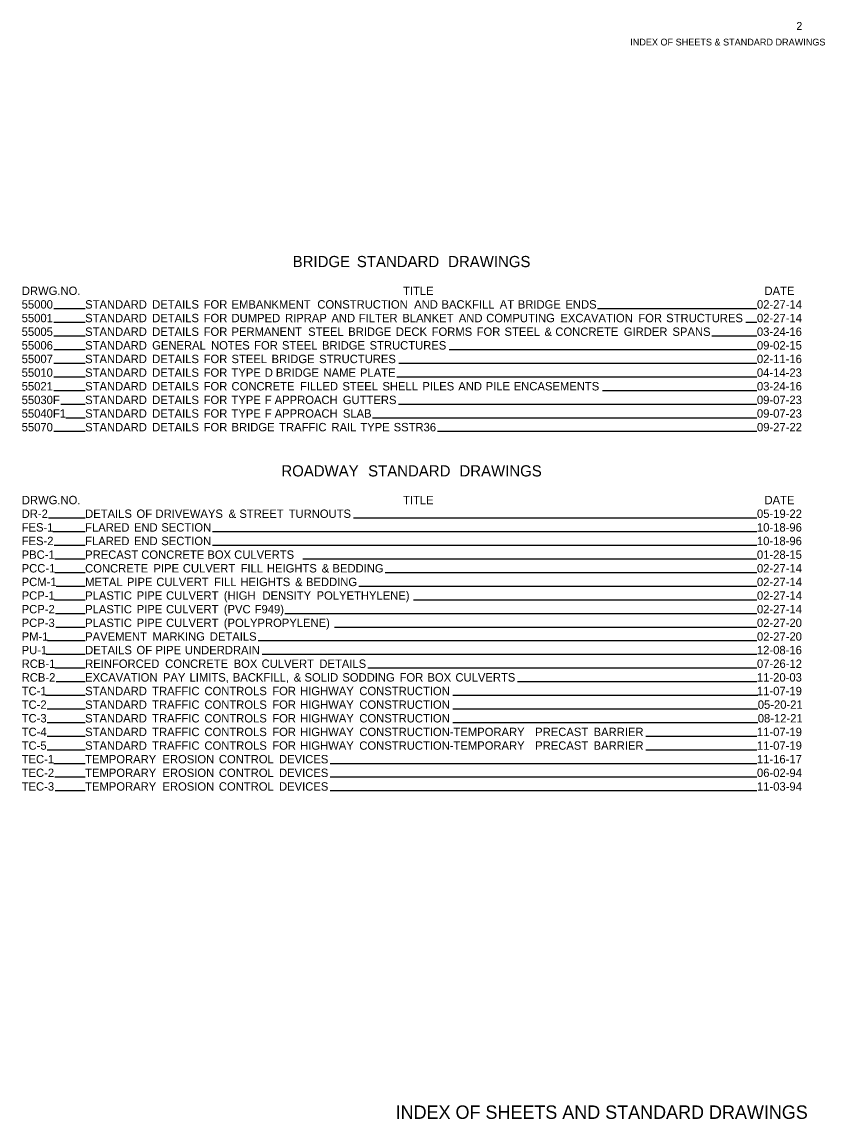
# Model space of a CAD drawing. Extents: x 1334719.7 to 1334768.4, y 402732.4 to 402752.
# Drawn here: x 1334754.07 to 1334768.42, y 402732.35 to 402751.96 of the extents above; entities that cross this region are included whole.
import ezdxf

# ---------------------------------------------------------------- set-up
doc = ezdxf.new("R2010")
doc.units = 0
for name, color, linetype in [('Default', 7, 'Continuous'), ('R_No Plot', 7, 'Continuous'), ('T_Drafting', 7, 'Continuous')]:
    doc.layers.add(name, color=color, linetype=linetype)

msp = doc.modelspace()

# ---------------------------------------------------------------- linework, layer by layer
at = {"layer": 'Default'}
for p, q in [((1334754.642, 402746.84), (1334755.203, 402746.84)), ((1334764.358, 402746.84), (1334767.208, 402746.84)), ((1334754.642, 402746.596), (1334755.203, 402746.596)), ((1334767.009, 402746.596), (1334767.208, 402746.596)), ((1334754.642, 402746.352), (1334755.203, 402746.352)), ((1334766.4, 402746.352), (1334767.207, 402746.352)), ((1334754.642, 402746.108), (1334755.203, 402746.108)), ((1334761.709, 402746.108), (1334767.207, 402746.108)), ((1334754.642, 402745.865), (1334755.203, 402745.865)), ((1334760.808, 402745.865), (1334767.207, 402745.865)), ((1334754.642, 402745.621), (1334755.203, 402745.621)), ((1334760.77, 402745.621), (1334767.207, 402745.621)), ((1334754.642, 402745.377), (1334755.203, 402745.377)), ((1334764.449, 402745.377), (1334767.207, 402745.377)), ((1334754.77, 402745.133), (1334755.203, 402745.133)), ((1334760.801, 402745.133), (1334767.207, 402745.133)), ((1334754.858, 402744.89), (1334755.203, 402744.89)), ((1334760.335, 402744.89), (1334767.207, 402744.89)), ((1334754.642, 402744.646), (1334755.203, 402744.646)), ((1334761.501, 402744.646), (1334767.208, 402744.646)), ((1334754.547, 402743.098), (1334755.203, 402743.098)), ((1334759.996, 402743.098), (1334767.208, 402743.098)), ((1334754.625, 402742.854), (1334755.203, 402742.854)), ((1334757.481, 402742.854), (1334767.207, 402742.854)), ((1334754.652, 402742.611), (1334755.203, 402742.611)), ((1334757.481, 402742.611), (1334767.207, 402742.611)), ((1334754.66, 402742.367), (1334755.203, 402742.367)), ((1334759.094, 402742.367), (1334767.208, 402742.367)), ((1334754.66, 402742.123), (1334755.203, 402742.123)), ((1334760.567, 402742.123), (1334767.208, 402742.123)), ((1334754.683, 402741.879), (1334755.203, 402741.879)), ((1334760.093, 402741.879), (1334767.208, 402741.879)), ((1334754.648, 402741.636), (1334755.203, 402741.636)), ((1334761.069, 402741.636), (1334767.208, 402741.636)), ((1334754.676, 402741.392), (1334755.203, 402741.392)), ((1334758.774, 402741.392), (1334767.208, 402741.392)), ((1334754.677, 402741.148), (1334755.203, 402741.148)), ((1334759.656, 402741.148), (1334767.208, 402741.148)), ((1334754.532, 402740.904), (1334755.203, 402740.904)), ((1334758.296, 402740.904), (1334767.208, 402740.904)), ((1334754.508, 402740.661), (1334755.203, 402740.661)), ((1334758.368, 402740.661), (1334767.208, 402740.661)), ((1334754.66, 402740.417), (1334755.203, 402740.417)), ((1334760.253, 402740.417), (1334767.207, 402740.417)), ((1334754.687, 402740.173), (1334755.203, 402740.173)), ((1334762.929, 402740.173), (1334767.207, 402740.173)), ((1334754.497, 402739.929), (1334755.203, 402739.929)), ((1334761.776, 402739.929), (1334767.222, 402739.929)), ((1334754.524, 402739.686), (1334755.203, 402739.686)), ((1334761.776, 402739.686), (1334767.222, 402739.686)), ((1334754.526, 402739.442), (1334755.203, 402739.442)), ((1334761.776, 402739.442), (1334767.222, 402739.442)), ((1334754.525, 402739.198), (1334755.203, 402739.198)), ((1334765.221, 402739.198), (1334767.207, 402739.198)), ((1334754.527, 402738.954), (1334755.203, 402738.954)), ((1334765.221, 402738.954), (1334767.207, 402738.954)), ((1334754.642, 402738.711), (1334755.203, 402738.711)), ((1334759.58, 402738.711), (1334767.207, 402738.711)), ((1334754.664, 402738.467), (1334755.203, 402738.467)), ((1334759.58, 402738.467), (1334767.208, 402738.467)), ((1334754.665, 402738.223), (1334755.203, 402738.223)), ((1334759.58, 402738.223), (1334767.208, 402738.223))]:
    msp.add_line(p, q, dxfattribs=at)

# ---------------------------------------------------------------- texts
for s, height, p in [('BRIDGE', 0.2, (1334758.911, 402747.581)), (' STANDARD', 0.2, (1334759.984, 402747.581)), (' DRAWINGS', 0.2, (1334761.615, 402747.581)), ('DRWG.NO.', 0.15, (1334754.072, 402747.083)), ('TITLE', 0.15, (1334760.883, 402747.083)), ('DATE', 0.15, (1334767.342, 402747.083)), ('55000', 0.15, (1334754.069, 402746.84)), ('STANDARD', 0.15, (1334755.203, 402746.84)), (' DETAILS', 0.15, (1334756.345, 402746.84)), (' FOR', 0.15, (1334757.265, 402746.84)), (' EMBANKMENT', 0.15, (1334757.763, 402746.84)), (' CONSTRUCTION', 0.15, (1334759.296, 402746.84)), (' AND', 0.15, (1334761.026, 402746.84)), (' BACKFILL', 0.15, (1334761.515, 402746.84)), (' AT', 0.15, (1334762.556, 402746.84)), (' BRIDGE', 0.15, (1334762.878, 402746.84)), (' ENDS', 0.15, (1334763.729, 402746.84)), ('02-27-14', 0.15, (1334767.208, 402746.84)), ('55001', 0.15, (1334754.069, 402746.596)), ('STANDARD', 0.15, (1334755.203, 402746.596)), (' DETAILS', 0.15, (1334756.345, 402746.596)), (' FOR', 0.15, (1334757.265, 402746.596)), (' DUMPED', 0.15, (1334757.763, 402746.596)), (' RIPRAP', 0.15, (1334758.719, 402746.596)), (' AND', 0.15, (1334759.548, 402746.596)), (' FILTER', 0.15, (1334760.038, 402746.596)), (' BLANKET', 0.15, (1334760.815, 402746.596)), (' AND', 0.15, (1334761.824, 402746.596)), (' COMPUTING', 0.15, (1334762.314, 402746.596)), (' EXCAVATION', 0.15, (1334763.64, 402746.596)), (' FOR', 0.15, (1334765.032, 402746.596)), (' STRUCTURES', 0.15, (1334765.53, 402746.596)), ('02-27-14', 0.15, (1334767.208, 402746.596)), ('55005', 0.15, (1334754.069, 402746.352)), ('STANDARD', 0.15, (1334755.203, 402746.352)), (' DETAILS', 0.15, (1334756.345, 402746.352)), (' FOR', 0.15, (1334757.265, 402746.352)), (' PERMANENT', 0.15, (1334757.763, 402746.352)), (' STEEL', 0.15, (1334759.133, 402746.352)), (' BRIDGE', 0.15, (1334759.848, 402746.352)), (' DECK', 0.15, (1334760.699, 402746.352)), (' FORMS', 0.15, (1334761.339, 402746.352)), (' FOR', 0.15, (1334762.143, 402746.352)), (' STEEL', 0.15, (1334762.641, 402746.352)), (' &', 0.15, (1334763.355, 402746.352)), (' CONCRETE', 0.15, (1334763.549, 402746.352)), (' GIRDER', 0.15, (1334764.772, 402746.352)), (' SPANS', 0.15, (1334765.642, 402746.352)), ('03-24-16', 0.15, (1334767.207, 402746.352)), ('55006', 0.15, (1334754.069, 402746.108)), ('STANDARD', 0.15, (1334755.203, 402746.108)), (' GENERAL', 0.15, (1334756.345, 402746.108)), (' NOTES', 0.15, (1334757.397, 402746.108)), (' FOR', 0.15, (1334758.167, 402746.108)), (' STEEL', 0.15, (1334758.664, 402746.108)), (' BRIDGE', 0.15, (1334759.379, 402746.108)), (' STRUCTURES', 0.15, (1334760.23, 402746.108)), ('09-02-15', 0.15, (1334767.207, 402746.108)), ('55007', 0.15, (1334754.069, 402745.865)), ('STANDARD', 0.15, (1334755.203, 402745.865)), (' DETAILS', 0.15, (1334756.345, 402745.865)), (' FOR', 0.15, (1334757.265, 402745.865)), (' STEEL', 0.15, (1334757.763, 402745.865)), (' BRIDGE', 0.15, (1334758.478, 402745.865)), (' STRUCTURES', 0.15, (1334759.329, 402745.865)), ('02-11-16', 0.15, (1334767.207, 402745.865)), ('55010', 0.15, (1334754.069, 402745.621)), ('STANDARD', 0.15, (1334755.203, 402745.621)), (' DETAILS', 0.15, (1334756.345, 402745.621)), (' FOR', 0.15, (1334757.265, 402745.621)), (' TYPE', 0.15, (1334757.763, 402745.621)), (' D', 0.15, (1334758.358, 402745.621)), (' BRIDGE', 0.15, (1334758.556, 402745.621)), (' NAME', 0.15, (1334759.407, 402745.621)), (' PLATE', 0.15, (1334760.059, 402745.621)), ('04-14-23', 0.15, (1334767.207, 402745.621)), ('55021', 0.15, (1334754.069, 402745.377)), ('STANDARD', 0.15, (1334755.203, 402745.377)), (' DETAILS', 0.15, (1334756.345, 402745.377)), (' FOR', 0.15, (1334757.265, 402745.377)), (' CONCRETE', 0.15, (1334757.763, 402745.377)), (' FILLED', 0.15, (1334758.986, 402745.377)), (' STEEL', 0.15, (1334759.744, 402745.377)), (' SHELL', 0.15, (1334760.459, 402745.377)), (' PILES', 0.15, (1334761.173, 402745.377)), (' AND', 0.15, (1334761.815, 402745.377)), (' PILE', 0.15, (1334762.304, 402745.377)), (' ENCASEMENTS', 0.15, (1334762.806, 402745.377)), ('03-24-16', 0.15, (1334767.207, 402745.377)), ('55030F', 0.15, (1334754.069, 402745.133)), ('STANDARD', 0.15, (1334755.203, 402745.133)), (' DETAILS', 0.15, (1334756.345, 402745.133)), (' FOR', 0.15, (1334757.265, 402745.133)), (' TYPE', 0.15, (1334757.763, 402745.133)), (' F', 0.15, (1334758.358, 402745.133)), (' APPROACH', 0.15, (1334758.534, 402745.133)), (' GUTTERS', 0.15, (1334759.752, 402745.133)), ('09-07-23', 0.15, (1334767.207, 402745.133)), ('55040F1', 0.15, (1334754.069, 402744.89)), ('STANDARD', 0.15, (1334755.203, 402744.89)), (' DETAILS', 0.15, (1334756.345, 402744.89)), (' FOR', 0.15, (1334757.265, 402744.89)), (' TYPE', 0.15, (1334757.763, 402744.89)), (' F', 0.15, (1334758.358, 402744.89)), (' APPROACH', 0.15, (1334758.534, 402744.89)), (' SLAB', 0.15, (1334759.752, 402744.89)), ('09-07-23', 0.15, (1334767.207, 402744.89)), ('55070', 0.15, (1334754.069, 402744.646)), ('STANDARD', 0.15, (1334755.203, 402744.646)), (' DETAILS', 0.15, (1334756.345, 402744.646)), (' FOR', 0.15, (1334757.265, 402744.646)), (' BRIDGE', 0.15, (1334757.763, 402744.646)), (' TRAFFIC', 0.15, (1334758.614, 402744.646)), (' RAIL', 0.15, (1334759.549, 402744.646)), (' TYPE', 0.15, (1334760.065, 402744.646)), (' SSTR36', 0.15, (1334760.66, 402744.646)), ('09-27-22', 0.15, (1334767.208, 402744.646)), ('ROADWAY', 0.2, (1334758.709, 402743.839)), (' STANDARD', 0.2, (1334760.185, 402743.839)), (' DRAWINGS', 0.2, (1334761.817, 402743.839)), ('DRWG.NO.', 0.15, (1334754.072, 402743.342)), ('TITLE', 0.15, (1334760.883, 402743.342)), ('DATE', 0.15, (1334767.342, 402743.342)), ('DR-2', 0.15, (1334754.069, 402743.098)), ('DETAILS', 0.15, (1334755.203, 402743.098)), (' OF', 0.15, (1334756.065, 402743.098)), (' DRIVEWAYS', 0.15, (1334756.405, 402743.098)), (' &', 0.15, (1334757.71, 402743.098)), (' STREET', 0.15, (1334757.903, 402743.098)), (' TURNOUTS', 0.15, (1334758.784, 402743.098)), ('05-19-22', 0.15, (1334767.208, 402743.098)), ('FES-1', 0.15, (1334754.069, 402742.854)), ('FLARED', 0.15, (1334755.203, 402742.854)), (' END', 0.15, (1334756.019, 402742.854)), (' SECTION', 0.15, (1334756.508, 402742.854)), ('10-18-96', 0.15, (1334767.207, 402742.854)), ('FES-2', 0.15, (1334754.069, 402742.611)), ('FLARED', 0.15, (1334755.203, 402742.611)), (' END', 0.15, (1334756.019, 402742.611)), (' SECTION', 0.15, (1334756.508, 402742.611)), ('10-18-96', 0.15, (1334767.207, 402742.611)), ('PBC-1', 0.15, (1334754.069, 402742.367)), ('PRECAST CONCRETE BOX CULVERTS', 0.15, (1334755.203, 402742.367)), ('01-28-15', 0.15, (1334767.207, 402742.367)), ('PCC-1', 0.15, (1334754.069, 402742.123)), ('CONCRETE', 0.15, (1334755.203, 402742.123)), (' PIPE', 0.15, (1334756.368, 402742.123)), (' CULVERT', 0.15, (1334756.893, 402742.123)), (' FILL', 0.15, (1334757.925, 402742.123)), (' HEIGHTS', 0.15, (1334758.395, 402742.123)), (' &', 0.15, (1334759.374, 402742.123)), (' BEDDING', 0.15, (1334759.567, 402742.123)), ('02-27-14', 0.15, (1334767.208, 402742.123)), ('PCM-1', 0.15, (1334754.069, 402741.879)), ('METAL', 0.15, (1334755.203, 402741.879)), (' PIPE', 0.15, (1334755.894, 402741.879)), (' CULVERT', 0.15, (1334756.419, 402741.879)), (' FILL', 0.15, (1334757.451, 402741.879)), (' HEIGHTS', 0.15, (1334757.921, 402741.879)), (' &', 0.15, (1334758.9, 402741.879)), (' BEDDING', 0.15, (1334759.093, 402741.879)), ('02-27-14', 0.15, (1334767.208, 402741.879)), ('PCP-1', 0.15, (1334754.069, 402741.636)), ('PLASTIC', 0.15, (1334755.203, 402741.636)), (' PIPE', 0.15, (1334756.068, 402741.636)), (' CULVERT', 0.15, (1334756.593, 402741.636)), (' (HIGH', 0.15, (1334757.625, 402741.636)), ('  DENSITY', 0.15, (1334758.26, 402741.636)), (' POLYETHYLENE)', 0.15, (1334759.283, 402741.636)), ('02-27-14', 0.15, (1334767.208, 402741.636)), ('PCP-2', 0.15, (1334754.069, 402741.392)), ('PLASTIC', 0.15, (1334755.203, 402741.392)), (' PIPE', 0.15, (1334756.068, 402741.392)), (' CULVERT', 0.15, (1334756.593, 402741.392)), (' (PVC', 0.15, (1334757.625, 402741.392)), (' F949)', 0.15, (1334758.176, 402741.392)), ('02-27-14', 0.15, (1334767.208, 402741.392)), ('PCP-3', 0.15, (1334754.069, 402741.148)), ('PLASTIC', 0.15, (1334755.203, 402741.148)), (' PIPE', 0.15, (1334756.068, 402741.148)), (' CULVERT', 0.15, (1334756.593, 402741.148)), (' (POLYPROPYLENE)', 0.15, (1334757.625, 402741.148)), ('02-27-20', 0.15, (1334767.208, 402741.148)), ('PM-1', 0.15, (1334754.069, 402740.904)), ('PAVEMENT', 0.15, (1334755.203, 402740.904)), (' MARKING', 0.15, (1334756.352, 402740.904)), (' DETAILS', 0.15, (1334757.375, 402740.904)), ('02-27-20', 0.15, (1334767.208, 402740.904)), ('PU-1', 0.15, (1334754.069, 402740.661)), ('DETAILS', 0.15, (1334755.203, 402740.661)), (' OF', 0.15, (1334756.065, 402740.661)), (' PIPE', 0.15, (1334756.405, 402740.661)), (' UNDERDRAIN', 0.15, (1334756.93, 402740.661)), ('12-08-16', 0.15, (1334767.207, 402740.661)), ('RCB-1', 0.15, (1334754.069, 402740.417)), ('REINFORCED', 0.15, (1334755.203, 402740.417)), (' CONCRETE', 0.15, (1334756.577, 402740.417)), (' BOX', 0.15, (1334757.801, 402740.417)), (' CULVERT', 0.15, (1334758.3, 402740.417)), (' DETAILS', 0.15, (1334759.332, 402740.417)), ('07-26-12', 0.15, (1334767.208, 402740.417)), ('RCB-2', 0.15, (1334754.069, 402740.173)), ('EXCAVATION', 0.15, (1334755.203, 402740.173)), (' PAY', 0.15, (1334756.537, 402740.173)), (' LIMITS,', 0.15, (1334757.013, 402740.173)), (' BACKFILL,', 0.15, (1334757.786, 402740.173)), (' &', 0.15, (1334758.874, 402740.173)), (' SOLID', 0.15, (1334759.067, 402740.173)), (' SODDING', 0.15, (1334759.743, 402740.173)), (' FOR', 0.15, (1334760.766, 402740.173)), (' BOX', 0.15, (1334761.264, 402740.173)), (' CULVERTS', 0.15, (1334761.764, 402740.173)), ('11-20-03', 0.15, (1334767.207, 402740.173)), ('TC-1', 0.15, (1334754.069, 402739.929)), ('STANDARD', 0.15, (1334755.203, 402739.929)), (' TRAFFIC', 0.15, (1334756.345, 402739.929)), (' CONTROLS', 0.15, (1334757.279, 402739.929)), (' FOR', 0.15, (1334758.491, 402739.929)), (' HIGHWAY', 0.15, (1334758.989, 402739.929)), (' CONSTRUCTION', 0.15, (1334760.047, 402739.929)), ('11-07-19', 0.15, (1334767.207, 402739.929)), ('TC-2', 0.15, (1334754.069, 402739.686)), ('STANDARD', 0.15, (1334755.203, 402739.686)), (' TRAFFIC', 0.15, (1334756.345, 402739.686)), (' CONTROLS', 0.15, (1334757.279, 402739.686)), (' FOR', 0.15, (1334758.491, 402739.686)), (' HIGHWAY', 0.15, (1334758.989, 402739.686)), (' CONSTRUCTION', 0.15, (1334760.047, 402739.686)), ('05-20-21', 0.15, (1334767.222, 402739.686)), ('TC-3', 0.15, (1334754.069, 402739.442)), ('STANDARD', 0.15, (1334755.203, 402739.442)), (' TRAFFIC', 0.15, (1334756.345, 402739.442)), (' CONTROLS', 0.15, (1334757.279, 402739.442)), (' FOR', 0.15, (1334758.491, 402739.442)), (' HIGHWAY', 0.15, (1334758.989, 402739.442)), (' CONSTRUCTION', 0.15, (1334760.047, 402739.442)), ('08-12-21', 0.15, (1334767.222, 402739.442)), ('TC-4', 0.15, (1334754.069, 402739.198)), ('STANDARD', 0.15, (1334755.203, 402739.198)), (' TRAFFIC', 0.15, (1334756.345, 402739.198)), (' CONTROLS', 0.15, (1334757.279, 402739.198)), (' FOR', 0.15, (1334758.491, 402739.198)), (' HIGHWAY', 0.15, (1334758.989, 402739.198)), (' CONSTRUCTION-TEMPORARY', 0.15, (1334760.047, 402739.198)), (' PRECAST', 0.15, (1334763.189, 402739.198)), (' BARRIER', 0.15, (1334764.233, 402739.198)), ('11-07-19', 0.15, (1334767.207, 402739.198)), ('TC-5', 0.15, (1334754.069, 402738.954)), ('STANDARD', 0.15, (1334755.203, 402738.954)), (' TRAFFIC', 0.15, (1334756.345, 402738.954)), (' CONTROLS', 0.15, (1334757.279, 402738.954)), (' FOR', 0.15, (1334758.491, 402738.954)), (' HIGHWAY', 0.15, (1334758.989, 402738.954)), (' CONSTRUCTION-TEMPORARY', 0.15, (1334760.047, 402738.954)), (' PRECAST', 0.15, (1334763.189, 402738.954)), (' BARRIER', 0.15, (1334764.233, 402738.954)), ('11-07-19', 0.15, (1334767.207, 402738.954)), ('TEC-1', 0.15, (1334754.069, 402738.711)), ('TEMPORARY', 0.15, (1334755.203, 402738.711)), (' EROSION', 0.15, (1334756.529, 402738.711)), (' CONTROL', 0.15, (1334757.537, 402738.711)), (' DEVICES', 0.15, (1334758.612, 402738.711)), ('11-16-17', 0.15, (1334767.207, 402738.711)), ('TEC-2', 0.15, (1334754.069, 402738.467)), ('TEMPORARY', 0.15, (1334755.203, 402738.467)), (' EROSION', 0.15, (1334756.529, 402738.467)), (' CONTROL', 0.15, (1334757.537, 402738.467)), (' DEVICES', 0.15, (1334758.612, 402738.467)), ('06-02-94', 0.15, (1334767.208, 402738.467)), ('TEC-3', 0.15, (1334754.069, 402738.223)), ('TEMPORARY', 0.15, (1334755.203, 402738.223)), (' EROSION', 0.15, (1334756.529, 402738.223)), (' CONTROL', 0.15, (1334757.537, 402738.223)), (' DEVICES', 0.15, (1334758.612, 402738.223)), ('11-03-94', 0.15, (1334767.208, 402738.223)), ('INDEX OF SHEETS AND STANDARD DRAWINGS', 0.24, (1334760.751, 402732.356))]:
    msp.add_text(s, height=height, dxfattribs=at).set_placement(p)
at = {"layer": 'R_No Plot'}
msp.add_text('2', height=0.14, rotation=360, dxfattribs=at).set_placement((1334767.913, 402751.822))
at = {"layer": 'T_Drafting'}
msp.add_text('INDEX OF SHEETS & STANDARD DRAWINGS', height=0.12132, dxfattribs=at).set_placement((1334764.943, 402751.543))

doc.saveas('drawing.dxf')
